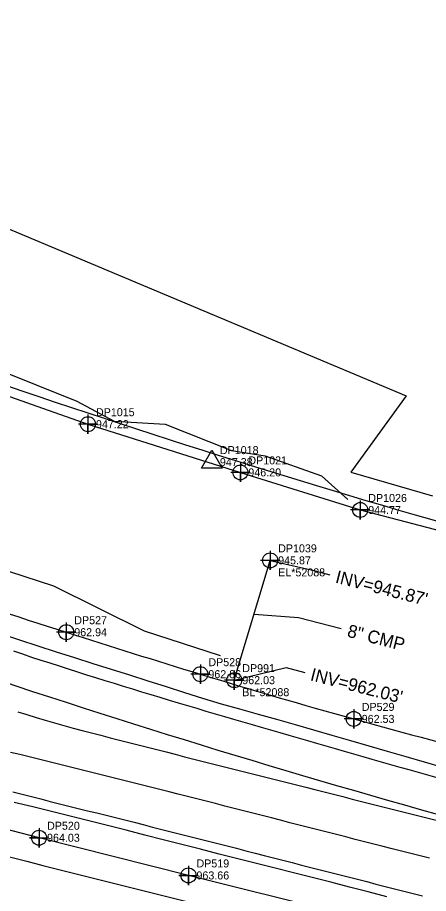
# Model space of a CAD drawing. Extents: x 1182322 to 1186765, y 572295 to 575411.
# Drawn here: x 1185469.1 to 1185597.5, y 573824.9 to 574098.5 of the extents above; entities that cross this region are included whole.
import ezdxf

# ---------------------------------------------------------------- set-up
doc = ezdxf.new("R2010")
doc.units = 0
for name, color, linetype in [('COGO Default Chain', 7, 'Continuous'), ('Exist Guardrail', 7, 'Continuous'), ('Exist Guardrail Cable Guide Rail', 7, 'Continuous'), ('Exist Guardrail Cable Guide Rail Cogo Elevation', 7, 'Continuous'), ('Exist Guardrail Cable Guide Rail Cogo Number', 7, 'Continuous'), ('Exist Guardrail Cable Guide Rail Cogo Point CELL', 7, 'Continuous'), ('Exist Guardrail Cogo Elevation', 7, 'Continuous'), ('Exist Guardrail Cogo Number', 7, 'Continuous'), ('Exist Guardrail Cogo Point CELL', 7, 'Continuous'), ('Exist Horizontal Alignment', 7, 'Continuous'), ('Exist Other Culture Fence Line', 7, 'Continuous'), ('Exist Other Culture Fence Line Cogo Elevation', 7, 'Continuous'), ('Exist Other Culture Fence Line Cogo Number', 7, 'Continuous'), ('Exist Other Culture Fence Line Cogo Point CELL', 7, 'Continuous'), ('Exist Right of Way Line', 7, 'Continuous'), ('Exist Right of Way Monument CELL', 7, 'Continuous'), ('Exist Right of Way Monument Cogo Elevation', 7, 'Continuous'), ('Exist Right of Way Monument Cogo Number', 7, 'Continuous'), ('Exist Roads EOP', 7, 'Continuous'), ('Exist Roads EOT', 7, 'Continuous'), ('Exist Structure Minor Pipes CMP 8 Inch', 7, 'Continuous'), ('Exist Structure Minor Pipes CMP 8 Inch Cogo Comment', 7, 'Continuous'), ('Exist Structure Minor Pipes CMP 8 Inch Cogo Elevation', 7, 'Continuous'), ('Exist Structure Minor Pipes CMP 8 Inch Cogo Number', 7, 'Continuous'), ('Exist Structure Minor Pipes CMP 8 Inch Cogo Point CELL', 7, 'Continuous'), ('Exist Structure Minor Pipes CMP 8 Inch Invert', 7, 'Continuous'), ('Exist Structure Minor Pipes CMP 8 Inch Leader', 7, 'Continuous'), ('Exist Structure Minor Pipes CMP 8 Inch Text', 7, 'Continuous'), ('Exist Vegetation Woods Line', 7, 'Continuous'), ('Sheet Layout Plan Border', 7, 'Continuous')]:
    doc.layers.add(name, color=color, linetype=linetype)

msp = doc.modelspace()

# ---------------------------------------------------------------- linework, layer by layer
at = {"layer": 'COGO Default Chain'}
for centre, radius, start, end in [((1186394.82, 576698.6), 2957.6, 249.39538, 256.24258), ((1192883.59, 603243.25), 30327.83, 255.640516, 256.263723)]:
    msp.add_arc(centre, radius, start, end, dxfattribs=at)
at = {"layer": 'Exist Guardrail'}
msp.add_spline([(1185390.3, 573940.07), (1185437.01, 573922.28), (1185484.33, 573906.54), (1185526.22, 573893.43), (1185574.13, 573879.46), (1185622.33, 573866.54), (1185670.88, 573853.88), (1185719.13, 573841.46), (1185767.43, 573829.33), (1185816.18, 573817.9), (1185864.94, 573807.26), (1185913.93, 573797.57), (1185963.25, 573788.74), (1186012.41, 573780.34), (1186049.41, 573774.82)], degree=3, dxfattribs=at)
at = {"layer": 'Exist Guardrail Cable Guide Rail'}
msp.add_lwpolyline([(1185615.35, 573807.21), (1185568.82, 573818.98), (1185522.5, 573830.57), (1185475.83, 573842.34), (1185444.88, 573850.35), (1185398.46, 573862.01), (1185351.94, 573873.71)], dxfattribs=at)
at = {"layer": 'Exist Guardrail Cable Guide Rail Cogo Point CELL'}
for points in [[(1185475.83, 573845.34), (1185475.83, 573839.34), (1185475.83, 573842.34), (1185472.83, 573842.34), (1185478.83, 573842.34)], [(1185522.5, 573833.57), (1185522.5, 573827.57), (1185522.5, 573830.57), (1185519.5, 573830.57), (1185525.5, 573830.57)]]:
    msp.add_lwpolyline(points, dxfattribs=at)
for centre in [(1185475.83, 573842.34), (1185522.5, 573830.57)]:
    msp.add_circle(centre, 2.34, dxfattribs=at)
at = {"layer": 'Exist Guardrail Cogo Point CELL'}
for points in [[(1185484.33, 573909.54), (1185484.33, 573903.54), (1185484.33, 573906.54), (1185487.33, 573906.54), (1185481.33, 573906.54)], [(1185526.22, 573896.43), (1185526.22, 573890.43), (1185526.22, 573893.43), (1185529.22, 573893.43), (1185523.22, 573893.43)], [(1185574.13, 573882.46), (1185574.13, 573876.46), (1185574.13, 573879.46), (1185577.13, 573879.46), (1185571.13, 573879.46)]]:
    msp.add_lwpolyline(points, dxfattribs=at)
for centre in [(1185484.33, 573906.54), (1185526.22, 573893.43), (1185574.13, 573879.46)]:
    msp.add_circle(centre, 2.34, dxfattribs=at)
at = {"layer": 'Exist Horizontal Alignment'}
for centre, radius, start, end in [((1186394.82, 576698.6), 2957.6, 249.39538, 256.24258), ((1192883.59, 603243.25), 30327.83, 255.640516, 256.263723)]:
    msp.add_arc(centre, radius, start, end, dxfattribs=at)
at = {"layer": 'Exist Other Culture Fence Line'}
msp.add_lwpolyline([(1184859.89, 574383.59), (1184869.68, 574315.09), (1184908.6, 574288.34), (1184956.03, 574255.54), (1185009.07, 574217.02), (1185046.56, 574193.02), (1185093.48, 574162.62), (1185152.72, 574124.64), (1185217.54, 574090.13), (1185270.37, 574062.3), (1185320.4, 574038.84), (1185375.89, 574014.29), (1185431.73, 573992.44), (1185491.11, 573971.52), (1185538.71, 573956.46), (1185576.16, 573944.72), (1185627.61, 573931.32)], dxfattribs=at)
at = {"layer": 'Exist Other Culture Fence Line Cogo Point CELL'}
for points in [[(1185491.11, 573974.52), (1185491.11, 573968.52), (1185491.11, 573971.52), (1185494.11, 573971.52), (1185488.11, 573971.52)], [(1185538.71, 573959.46), (1185538.71, 573953.46), (1185538.71, 573956.46), (1185541.71, 573956.46), (1185535.71, 573956.46)], [(1185576.16, 573947.72), (1185576.16, 573941.72), (1185576.16, 573944.72), (1185579.16, 573944.72), (1185573.16, 573944.72)]]:
    msp.add_lwpolyline(points, dxfattribs=at)
for centre in [(1185491.11, 573971.52), (1185538.71, 573956.46), (1185576.16, 573944.72)]:
    msp.add_circle(centre, 2.34, dxfattribs=at)
at = {"layer": 'Exist Right of Way Line'}
msp.add_arc((1186394.82, 576698.6), 2869.6, 249.39538, 256.24258, dxfattribs=at)
at = {"layer": 'Exist Right of Way Monument CELL'}
msp.add_line((1185529.82, 573959.67), (1185529.82, 573959.67), dxfattribs=at)
msp.add_lwpolyline([(1185526.57, 573957.78), (1185529.82, 573963.42), (1185533.07, 573957.78)], close=True, dxfattribs=at)
at = {"layer": 'Exist Roads EOP'}
for points in [[(1185464.06, 573905.99), (1185469.76, 573904.12), (1185475.46, 573902.24), (1185481.17, 573900.39), (1185486.89, 573898.59), (1185492.61, 573896.79), (1185498.34, 573894.99), (1185504.06, 573893.2), (1185509.78, 573891.39), (1185515.5, 573889.57), (1185521.22, 573887.75), (1185526.93, 573885.92), (1185532.69, 573884.22), (1185538.46, 573882.61), (1185544.24, 573880.99), (1185550.02, 573879.38), (1185555.79, 573877.74), (1185561.55, 573876.05), (1185567.31, 573874.37), (1185573.07, 573872.68), (1185578.83, 573871), (1185584.6, 573869.36), (1185590.37, 573867.72), (1185596.14, 573866.08), (1185601.91, 573864.43)], [(1185584.42, 573823.93), (1185578.61, 573825.43), (1185572.8, 573826.92), (1185566.99, 573828.42), (1185561.18, 573829.91), (1185555.36, 573831.39), (1185549.55, 573832.86), (1185543.73, 573834.32), (1185537.91, 573835.79), (1185532.09, 573837.26), (1185526.27, 573838.73), (1185520.46, 573840.2), (1185514.65, 573841.68), (1185508.83, 573843.17), (1185503.02, 573844.66), (1185497.21, 573846.15), (1185491.4, 573847.64), (1185485.58, 573849.1), (1185479.75, 573850.53), (1185473.92, 573851.96), (1185468.1, 573853.39)]]:
    msp.add_lwpolyline(points, dxfattribs=at)
at = {"layer": 'Exist Roads EOT'}
for points in [[(1185467.83, 573900.69), (1185470.68, 573899.74), (1185473.52, 573898.79), (1185476.37, 573897.86), (1185479.23, 573896.93), (1185482.08, 573896), (1185484.94, 573895.09), (1185487.79, 573894.17), (1185490.65, 573893.26), (1185493.51, 573892.36), (1185496.38, 573891.48), (1185499.25, 573890.6), (1185502.12, 573889.72), (1185504.98, 573888.84), (1185507.85, 573887.96), (1185510.72, 573887.08), (1185513.59, 573886.21), (1185516.46, 573885.34), (1185519.33, 573884.46), (1185522.21, 573883.61), (1185525.09, 573882.77), (1185527.97, 573881.92), (1185530.85, 573881.08), (1185533.73, 573880.24), (1185536.61, 573879.4), (1185539.48, 573878.56), (1185542.36, 573877.71), (1185545.24, 573876.87), (1185548.12, 573876.03), (1185551, 573875.19), (1185553.88, 573874.35), (1185556.76, 573873.51), (1185559.64, 573872.67), (1185562.53, 573871.84), (1185565.41, 573871.01), (1185568.29, 573870.18), (1185571.18, 573869.36), (1185574.06, 573868.53), (1185576.94, 573867.7), (1185579.83, 573866.88), (1185582.71, 573866.06), (1185585.6, 573865.24), (1185588.49, 573864.43), (1185591.38, 573863.61), (1185594.26, 573862.8), (1185597.15, 573861.98), (1185600.04, 573861.17)], [(1185469.16, 573881.67), (1185472.04, 573880.8), (1185474.91, 573879.94), (1185477.78, 573879.08), (1185480.66, 573878.22), (1185483.54, 573877.39), (1185486.44, 573876.62), (1185489.34, 573875.86), (1185492.24, 573875.1), (1185495.15, 573874.34), (1185498.05, 573873.6), (1185500.96, 573872.86), (1185503.87, 573872.12), (1185506.77, 573871.38), (1185509.68, 573870.63), (1185512.59, 573869.89), (1185515.49, 573869.14), (1185518.4, 573868.4), (1185521.31, 573867.65), (1185524.21, 573866.92), (1185527.12, 573866.19), (1185530.04, 573865.46), (1185532.95, 573864.74), (1185535.86, 573864.01), (1185538.77, 573863.28), (1185541.68, 573862.55), (1185544.59, 573861.82), (1185547.49, 573861.08), (1185550.4, 573860.35), (1185553.31, 573859.61), (1185556.22, 573858.87), (1185559.13, 573858.13), (1185562.03, 573857.4), (1185564.94, 573856.66), (1185567.85, 573855.92), (1185570.76, 573855.18), (1185573.67, 573854.44), (1185576.57, 573853.71), (1185579.48, 573852.97), (1185582.39, 573852.24), (1185585.3, 573851.51), (1185588.21, 573850.79), (1185591.12, 573850.06), (1185594.03, 573849.33), (1185596.94, 573848.6), (1185599.85, 573847.88)], [(1185597.83, 573835.98), (1185594.92, 573836.7), (1185592.01, 573837.42), (1185589.09, 573838.14), (1185586.18, 573838.87), (1185583.28, 573839.61), (1185580.37, 573840.36), (1185577.46, 573841.1), (1185574.56, 573841.84), (1185571.65, 573842.59), (1185568.74, 573843.33), (1185565.84, 573844.07), (1185562.93, 573844.81), (1185560.02, 573845.56), (1185557.12, 573846.3), (1185554.21, 573847.04), (1185551.3, 573847.78), (1185548.4, 573848.53), (1185545.49, 573849.27), (1185542.59, 573850.01), (1185539.68, 573850.76), (1185536.77, 573851.5), (1185533.87, 573852.24), (1185530.96, 573852.99), (1185528.05, 573853.73), (1185525.15, 573854.47), (1185522.24, 573855.22), (1185519.33, 573855.96), (1185516.43, 573856.7), (1185513.52, 573857.44), (1185510.61, 573858.17), (1185507.7, 573858.89), (1185504.79, 573859.62), (1185501.88, 573860.34), (1185498.96, 573861.07), (1185496.05, 573861.8), (1185493.14, 573862.52), (1185490.23, 573863.25), (1185487.32, 573863.97), (1185484.41, 573864.7), (1185481.5, 573865.42), (1185478.59, 573866.15), (1185475.68, 573866.87), (1185472.76, 573867.59), (1185469.85, 573868.3), (1185466.93, 573869.01)], [(1185467.68, 573856.7), (1185470.59, 573855.96), (1185473.49, 573855.21), (1185476.39, 573854.46), (1185479.3, 573853.69), (1185482.2, 573852.93), (1185485.1, 573852.17), (1185488.02, 573851.47), (1185490.94, 573850.78), (1185493.85, 573850.08), (1185496.77, 573849.36), (1185499.67, 573848.63), (1185502.58, 573847.89), (1185505.49, 573847.16), (1185508.4, 573846.43), (1185511.31, 573845.69), (1185514.22, 573844.96), (1185517.13, 573844.22), (1185520.03, 573843.48), (1185522.94, 573842.74), (1185525.85, 573842), (1185528.76, 573841.27), (1185531.67, 573840.53), (1185534.57, 573839.79), (1185537.48, 573839.04), (1185540.38, 573838.29), (1185543.29, 573837.54), (1185546.19, 573836.79), (1185549.1, 573836.05), (1185552.01, 573835.3), (1185554.91, 573834.56), (1185557.82, 573833.82), (1185560.73, 573833.08), (1185563.63, 573832.34), (1185566.54, 573831.6), (1185569.45, 573830.87), (1185572.36, 573830.13), (1185575.26, 573829.39), (1185578.17, 573828.64), (1185581.07, 573827.89), (1185583.98, 573827.15), (1185586.89, 573826.41), (1185589.8, 573825.68), (1185592.71, 573824.94), (1185595.62, 573824.21)]]:
    msp.add_lwpolyline(points, dxfattribs=at)
at = {"layer": 'Exist Structure Minor Pipes CMP 8 Inch'}
msp.add_line((1185536.81, 573891.56), (1185548.02, 573928.98), dxfattribs=at)
at = {"layer": 'Exist Structure Minor Pipes CMP 8 Inch Cogo Point CELL'}
for points in [[(1185548.02, 573931.98), (1185548.02, 573925.98), (1185548.02, 573928.98), (1185551.02, 573928.98), (1185545.02, 573928.98)], [(1185536.81, 573894.56), (1185536.81, 573888.56), (1185536.81, 573891.56), (1185539.81, 573891.56), (1185533.81, 573891.56)]]:
    msp.add_lwpolyline(points, dxfattribs=at)
for centre in [(1185548.02, 573928.98), (1185536.81, 573891.56)]:
    msp.add_circle(centre, 2.34, dxfattribs=at)
at = {"layer": 'Exist Structure Minor Pipes CMP 8 Inch Leader'}
for points in [[(1185548.02, 573928.98), (1185560.88, 573925.99), (1185566.69, 573924.5)], [(1185543.05, 573912.18), (1185556.92, 573911.1), (1185570.24, 573907.69)], [(1185536.81, 573891.56), (1185553.06, 573895.48), (1185558.87, 573893.99)]]:
    msp.add_lwpolyline(points, dxfattribs=at)
at = {"layer": 'Exist Vegetation Woods Line'}
for points in [[(1185285.21, 574060.08), (1185309.44, 574048.8), (1185324.32, 574041.57), (1185335.88, 574032.48), (1185346.42, 574026.39), (1185371.67, 574015.48), (1185383.93, 574016.42), (1185406.75, 574007.88), (1185431.09, 573992.16), (1185441.34, 573990.08), (1185450.82, 573991.25), (1185462.07, 573988.89), (1185487.68, 573978.75), (1185499.33, 573972.48), (1185515.21, 573971.52), (1185535.92, 573963.33), (1185546.48, 573961.63), (1185564.05, 573955.41), (1185572.33, 573948.02)], [(1185532.46, 573899.18), (1185508.81, 573906.89), (1185480.4, 573920.97), (1185447.79, 573931.59), (1185421.14, 573940.88), (1185398.99, 573946.42), (1185381.34, 573956.52), (1185358.05, 573964.37), (1185322.3, 573984.13), (1185305.03, 573993.75), (1185291.23, 574004.86)]]:
    msp.add_lwpolyline(points, dxfattribs=at)
at = {"layer": 'Sheet Layout Plan Border'}
for p, q in [((1185590.56, 573980.35), (1185573.26, 573956.52)), ((1185573.26, 573956.52), (1185598.72, 573949.14))]:
    msp.add_line(p, q, dxfattribs=at)
msp.add_lwpolyline([(1185081.81, 574269.31), (1185310.78, 574097.8), (1185590.56, 573980.35)], dxfattribs=at)

# ---------------------------------------------------------------- texts
at = {"layer": 'Exist Guardrail Cable Guide Rail Cogo Elevation'}
for s, p in [('964.03', (1185478.33, 573841.09)), ('963.66', (1185525, 573829.32))]:
    msp.add_text(s, height=2.5, dxfattribs=at).set_placement(p)
at = {"layer": 'Exist Guardrail Cable Guide Rail Cogo Number'}
for s, p in [('DP520', (1185478.33, 573844.84)), ('DP519', (1185525, 573833.07))]:
    msp.add_text(s, height=2.5, dxfattribs=at).set_placement(p)
at = {"layer": 'Exist Guardrail Cogo Elevation'}
for s, p in [('962.94', (1185486.83, 573905.29)), ('962.86', (1185528.72, 573892.18)), ('962.53', (1185576.63, 573878.21))]:
    msp.add_text(s, height=2.5, dxfattribs=at).set_placement(p)
at = {"layer": 'Exist Guardrail Cogo Number'}
for s, p in [('DP527', (1185486.83, 573909.04)), ('DP528', (1185528.72, 573895.93)), ('DP529', (1185576.63, 573881.96))]:
    msp.add_text(s, height=2.5, dxfattribs=at).set_placement(p)
at = {"layer": 'Exist Other Culture Fence Line Cogo Elevation'}
for s, p in [('947.22', (1185493.61, 573970.27)), ('946.20', (1185541.21, 573955.21)), ('944.77', (1185578.66, 573943.47))]:
    msp.add_text(s, height=2.5, dxfattribs=at).set_placement(p)
at = {"layer": 'Exist Other Culture Fence Line Cogo Number'}
for s, p in [('DP1015', (1185493.61, 573974.02)), ('DP1021', (1185541.21, 573958.96)), ('DP1026', (1185578.66, 573947.22))]:
    msp.add_text(s, height=2.5, dxfattribs=at).set_placement(p)
at = {"layer": 'Exist Right of Way Monument Cogo Elevation'}
msp.add_text('947.38', height=2.5, dxfattribs=at).set_placement((1185532.32, 573958.42))
at = {"layer": 'Exist Right of Way Monument Cogo Number'}
msp.add_text('DP1018', height=2.5, dxfattribs=at).set_placement((1185532.32, 573962.17))
at = {"layer": 'Exist Structure Minor Pipes CMP 8 Inch Cogo Comment'}
for s, p in [('EL*52088', (1185550.52, 573923.98)), ('BL*52088', (1185539.31, 573886.56))]:
    msp.add_text(s, height=2.5, dxfattribs=at).set_placement(p)
at = {"layer": 'Exist Structure Minor Pipes CMP 8 Inch Cogo Elevation'}
for s, p in [('945.87', (1185550.52, 573927.73)), ('962.03', (1185539.31, 573890.31))]:
    msp.add_text(s, height=2.5, dxfattribs=at).set_placement(p)
at = {"layer": 'Exist Structure Minor Pipes CMP 8 Inch Cogo Number'}
for s, p in [('DP1039', (1185550.52, 573931.48)), ('DP991', (1185539.31, 573894.06))]:
    msp.add_text(s, height=2.5, dxfattribs=at).set_placement(p)
at = {"layer": 'Exist Structure Minor Pipes CMP 8 Inch Invert'}
for s, p in [("INV=945.87'", (1185568.14, 573922.07)), ("INV=962.03'", (1185560.31, 573891.56))]:
    msp.add_text(s, height=4, rotation=345.6405, dxfattribs=at).set_placement(p)
at = {"layer": 'Exist Structure Minor Pipes CMP 8 Inch Text'}
msp.add_text('8" CMP', height=4, rotation=345.6804, dxfattribs=at).set_placement((1185571.84, 573905.19))

doc.saveas('drawing.dxf')
